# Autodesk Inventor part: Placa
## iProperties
Shininess: 64.0
Length Units: 11272
Angle Units: 11279
Time Units: 11290
Mass Units: 11286
Length Display Precision: 3
Angle Display Precision: 2
Compacted: True
Part Number: Placa
Document SubType Name: Modeling
Created: 2005-06
Designer: Alek
Manufacturer: Standard
Standards Organization: Custom
Density: 0.0
Volumn: 0.0
Area: 0.0
PropertySet Name: Model Information
Control State: 0
Master: False
Checked Out: False
Author: Alek
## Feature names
1. Extrusion1
2. Hole1
